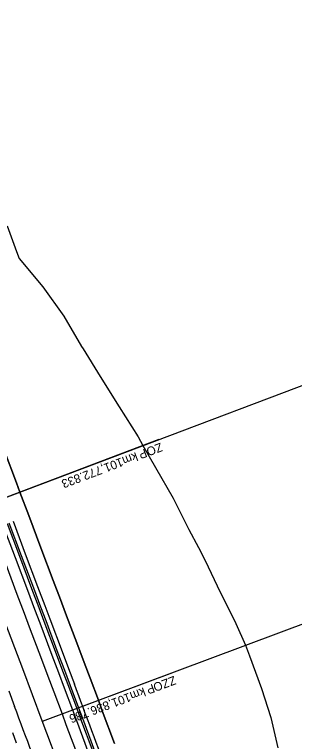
# Model space of a CAD drawing. Extents: x -678487 to -674601, y -1104811 to -1093295.
# Drawn here: x -676712.1 to -676631.7, y -1098531.5 to -1098322.4 of the extents above; entities that cross this region are included whole.
import ezdxf

# ---------------------------------------------------------------- set-up
doc = ezdxf.new("R2010")
doc.units = 0
for name, color, linetype in [('SOxxxxxx_Koleje_hlavní_body_Popis', 7, 'Continuous'), ('SOxxxxxx_Koleje_hlavní_body_Popis10', 7, 'Continuous'), ('SOxxxxxx_Koleje_LN_staničení_zaoblení_Popis', 7, 'Continuous'), ('SOxxxxxx_Koleje_LN_staničení_zaoblení_Popis10', 7, 'Continuous'), ('SOxxxxxx_Osa_bod_P', 7, 'Continuous'), ('SOxxxxxx_ŽSp_hrana', 7, 'Continuous'), ('SOxxxxxx_ŽSp_odvodnění', 7, 'Continuous'), ('SOxxxxxx_ŽSp_zářez_hrana', 7, 'Continuous'), ('SOxxxxxx_ŽSp_zářez_plocha', 7, 'Continuous')]:
    doc.layers.add(name, color=color, linetype=linetype)

msp = doc.modelspace()

# ---------------------------------------------------------------- linework, layer by layer
at = {"layer": 'SOxxxxxx_Koleje_hlavní_body_Popis'}
msp.add_line((-676726.65, -1098465.84), (-676670.54, -1098444.6), dxfattribs=at)
at = {"layer": 'SOxxxxxx_Koleje_hlavní_body_Popis10'}
msp.add_line((-676726.65, -1098465.84), (-676165.5, -1098253.44), dxfattribs=at)
at = {"layer": 'SOxxxxxx_Koleje_LN_staničení_zaoblení_Popis'}
msp.add_line((-676704.12, -1098525.69), (-676666.66, -1098511.67), dxfattribs=at)
at = {"layer": 'SOxxxxxx_Koleje_LN_staničení_zaoblení_Popis10'}
msp.add_line((-676704.12, -1098525.69), (-676329.52, -1098385.42), dxfattribs=at)
at = {"layer": 'SOxxxxxx_Osa_bod_P'}
msp.add_arc((-693563.22, -1104838.51), 18002.25, 14.227837, 20.731742, dxfattribs=at)
at = {"layer": 'SOxxxxxx_ŽSp_hrana'}
for points in [[(-676714.96, -1098479.78), (-676711.43, -1098489.14), (-676709.37, -1098494.6), (-676707.9, -1098498.5), (-676704.39, -1098507.86), (-676702.55, -1098512.76), (-676700.87, -1098517.23), (-676698.49, -1098523.58), (-676697.36, -1098526.6), (-676693.86, -1098535.97)], [(-676713.8, -1098516.98), (-676712.13, -1098521.45)]]:
    msp.add_lwpolyline(points, dxfattribs=at)
msp.add_arc((-693563.22, -1104838.51), 17996.24, 20.458312, 20.549796, dxfattribs=at)
at = {"layer": 'SOxxxxxx_ŽSp_odvodnění'}
for p, q in [((-676714.28, -1098468.83), (-676710.75, -1098478.19)), ((-676713.77, -1098468.63), (-676710.23, -1098477.99)), ((-676710.75, -1098478.19), (-676707.22, -1098487.55)), ((-676710.23, -1098477.99), (-676706.7, -1098487.36)), ((-676707.22, -1098487.55), (-676705.16, -1098493.01)), ((-676706.7, -1098487.36), (-676704.64, -1098492.82)), ((-676705.16, -1098493.01), (-676703.69, -1098496.91)), ((-676704.64, -1098492.82), (-676703.18, -1098496.72)), ((-676703.69, -1098496.91), (-676700.17, -1098506.28)), ((-676703.18, -1098496.72), (-676699.66, -1098506.09)), ((-676700.17, -1098506.28), (-676698.33, -1098511.18)), ((-676699.66, -1098506.09), (-676697.82, -1098510.99)), ((-676698.33, -1098511.18), (-676696.66, -1098515.65)), ((-676697.82, -1098510.99), (-676696.14, -1098515.45)), ((-676696.66, -1098515.65), (-676694.27, -1098522.01)), ((-676696.14, -1098515.45), (-676693.76, -1098521.81)), ((-676694.27, -1098522.01), (-676693.15, -1098525.02)), ((-676693.76, -1098521.81), (-676692.63, -1098524.83)), ((-676693.15, -1098525.02), (-676689.64, -1098534.39)), ((-676692.63, -1098524.83), (-676689.13, -1098534.2))]:
    msp.add_line(p, q, dxfattribs=at)
at = {"layer": 'SOxxxxxx_ŽSp_zářez_hrana'}
for p, q in [((-676714.27, -1098383.2), (-676711.52, -1098390.54)), ((-676711.52, -1098390.54), (-676710.76, -1098392.57)), ((-676710.76, -1098392.57), (-676703.97, -1098400.7)), ((-676703.97, -1098400.7), (-676697.99, -1098409.14)), ((-676697.99, -1098409.14), (-676692.87, -1098417.9)), ((-676692.87, -1098417.9), (-676692.42, -1098418.62)), ((-676692.42, -1098418.62), (-676687.5, -1098426.57)), ((-676687.5, -1098426.57), (-676682.03, -1098435.22)), ((-676682.03, -1098435.22), (-676676.65, -1098443.89)), ((-676676.65, -1098443.89), (-676675.24, -1098446.39)), ((-676675.24, -1098446.39), (-676671.64, -1098452.72)), ((-676715.15, -1098447.76), (-676711.6, -1098457.12)), ((-676671.64, -1098452.72), (-676666.59, -1098461.52)), ((-676711.6, -1098457.12), (-676710.6, -1098459.77)), ((-676710.6, -1098459.77), (-676708.06, -1098466.48)), ((-676666.59, -1098461.52), (-676662.07, -1098470.54)), ((-676708.06, -1098466.48), (-676704.53, -1098475.84)), ((-676715.48, -1098469.28), (-676711.95, -1098478.64)), ((-676712.57, -1098468.18), (-676709.04, -1098477.54)), ((-676662.07, -1098470.54), (-676659.3, -1098475.75)), ((-676709.04, -1098477.54), (-676705.51, -1098486.9)), ((-676704.53, -1098475.84), (-676700.99, -1098485.2)), ((-676659.3, -1098475.75), (-676657.33, -1098479.48)), ((-676711.95, -1098478.64), (-676708.42, -1098488)), ((-676657.33, -1098479.48), (-676653, -1098488.56)), ((-676700.99, -1098485.2), (-676698.94, -1098490.67)), ((-676708.42, -1098488), (-676706.36, -1098493.46)), ((-676705.51, -1098486.9), (-676703.45, -1098492.37)), ((-676653, -1098488.56), (-676650.64, -1098493.28)), ((-676703.45, -1098492.37), (-676701.98, -1098496.27)), ((-676698.94, -1098490.67), (-676697.47, -1098494.57)), ((-676706.36, -1098493.46), (-676704.89, -1098497.36)), ((-676650.64, -1098493.28), (-676648.51, -1098497.6)), ((-676701.98, -1098496.27), (-676698.46, -1098505.64)), ((-676697.47, -1098494.57), (-676693.95, -1098503.94)), ((-676704.89, -1098497.36), (-676701.37, -1098506.73)), ((-676648.51, -1098497.6), (-676645.77, -1098503.84)), ((-676693.95, -1098503.94), (-676692.11, -1098508.84)), ((-676645.77, -1098503.84), (-676644.61, -1098506.85)), ((-676701.37, -1098506.73), (-676699.53, -1098511.63)), ((-676698.46, -1098505.64), (-676696.62, -1098510.54)), ((-676644.61, -1098506.85), (-676641.15, -1098516.27)), ((-676692.11, -1098508.84), (-676690.43, -1098513.31)), ((-676696.62, -1098510.54), (-676694.94, -1098515.01)), ((-676699.53, -1098511.63), (-676697.86, -1098516.1)), ((-676690.43, -1098513.31), (-676688.05, -1098519.67)), ((-676697.86, -1098516.1), (-676695.47, -1098522.46)), ((-676641.15, -1098516.27), (-676638.48, -1098524.64)), ((-676688.05, -1098519.67), (-676686.92, -1098522.69)), ((-676695.47, -1098522.46), (-676694.35, -1098525.47)), ((-676686.92, -1098522.69), (-676683.41, -1098532.06)), ((-676694.35, -1098525.47), (-676690.84, -1098534.84)), ((-676638.48, -1098524.64), (-676638.17, -1098525.87)), ((-676638.17, -1098525.87), (-676636.48, -1098533.33)), ((-676712.76, -1098528.93), (-676711.64, -1098531.94))]:
    msp.add_line(p, q, dxfattribs=at)
msp.add_arc((-693563.22, -1104838.51), 18014.59, 20.458312, 20.549796, dxfattribs=at)
at = {"layer": 'SOxxxxxx_ŽSp_zářez_plocha'}
for points in [[(-676714.27, -1098383.2), (-676711.52, -1098390.54), (-676710.76, -1098392.57), (-676703.97, -1098400.7), (-676697.99, -1098409.14), (-676692.87, -1098417.9), (-676692.42, -1098418.62), (-676687.5, -1098426.57), (-676682.03, -1098435.22), (-676676.65, -1098443.89), (-676675.24, -1098446.39), (-676671.64, -1098452.72), (-676666.59, -1098461.52), (-676662.07, -1098470.54), (-676659.3, -1098475.75), (-676657.33, -1098479.48), (-676653, -1098488.56), (-676650.64, -1098493.28), (-676648.51, -1098497.6), (-676645.77, -1098503.84), (-676644.61, -1098506.85), (-676641.15, -1098516.27), (-676638.48, -1098524.64), (-676638.17, -1098525.87), (-676636.48, -1098533.33)], [(-676683.41, -1098532.06), (-676686.92, -1098522.69), (-676688.05, -1098519.67), (-676690.43, -1098513.31), (-676692.11, -1098508.84), (-676693.95, -1098503.94), (-676697.47, -1098494.57), (-676698.94, -1098490.67), (-676700.99, -1098485.2), (-676704.53, -1098475.84), (-676708.06, -1098466.48), (-676710.6, -1098459.77), (-676711.6, -1098457.12), (-676715.15, -1098447.76)]]:
    msp.add_lwpolyline(points, dxfattribs=at)

# ---------------------------------------------------------------- texts
at = {"layer": 'SOxxxxxx_Koleje_hlavní_body_Popis'}
for s, p in [('ZO', (-676670.18, -1098445.54)), (' km ', (-676676.43, -1098447.9)), ('P', (-676674.65, -1098447.23)), ('101,772.833', (-676681.49, -1098449.82))]:
    msp.add_text(s, height=2.5, rotation=200.7317, dxfattribs=at).set_placement(p)
at = {"layer": 'SOxxxxxx_Koleje_LN_staničení_zaoblení_Popis'}
for s, p in [('ZZO', (-676666.31, -1098512.6)), ('P', (-676672.42, -1098514.89)), (' km ', (-676674.2, -1098515.56)), ('101,836.786', (-676679.27, -1098517.46))]:
    msp.add_text(s, height=2.5, rotation=200.5282, dxfattribs=at).set_placement(p)

doc.saveas('drawing.dxf')
